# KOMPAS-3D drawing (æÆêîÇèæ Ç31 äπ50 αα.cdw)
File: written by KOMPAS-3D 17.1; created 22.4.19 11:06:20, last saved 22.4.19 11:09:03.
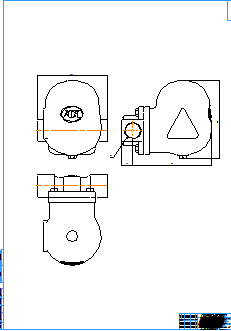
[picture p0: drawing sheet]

Sheet 1: A0, portrait

Title block, sheet 1: name: СТИМАКС А31 Ду50 р/р; material: Внимание! Данный продукт является объектом авторского права ООО «Торговый Дом АДЛ». / Запрещается изменение, копирование, распространение / (в том числе путем копирования на другие сайты и ресурсы в Интернете) / или любое иное использование информации и объектов без предварительного / согласия правообладателя (ООО «Торговый Дом АДЛ»).; mass: 31; sheets: 1; organisation: ООО "Торговый дом АДЛ"; sheet format: A0; stored path: \\adlc.lan\data\АДЛ_ПКД\3D-модели\ADL production\Конденсатоотводчики СТИМАКС\Поплавковые\Серия А31\KOMPAS 2D\СТИМАКС А31 Ду50 рр.cdw

Views: Вид 1, Проекционный вид 2, Проекционный вид 3
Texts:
  user
Dimensions and other numbers on the sheet: 250; 40; 284; 280; 1:1; 1; 31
